// Mitsubishi GX Works2 project: FX3U 485   PLC: FX3U/FX3UC
// FX3U 485

PROGRAM MAIN
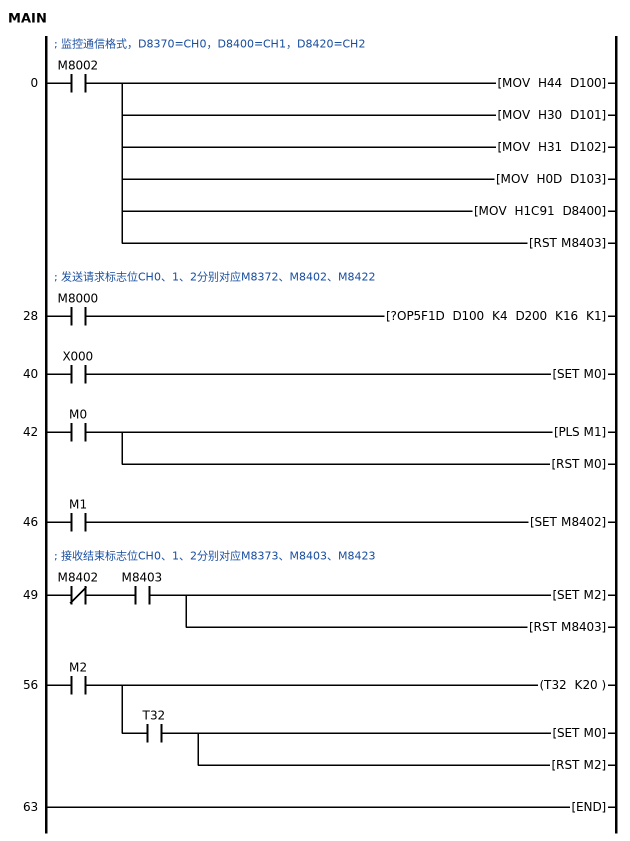
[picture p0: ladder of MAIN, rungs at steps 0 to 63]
; 监控通信格式，D8370=CH0，D8400=CH1，D8420=CH2
0     LD      M8002
      MOV     H44 D100
      MOV     H30 D101
      MOV     H31 D102
      MOV     H0D D103
      MOV     H1C91 D8400
      RST     M8403
; 发送请求标志位CH0、1、2分别对应M8372、M8402、M8422
28    LD      M8000
      ?OP5F1D D100 K4 D200 K16 K1
40    LD      X000
      SET     M0
42    LD      M0
      PLS     M1
      RST     M0
46    LD      M1
      SET     M8402
; 接收结束标志位CH0、1、2分别对应M8373、M8403、M8423
49    LDI     M8402
      AND     M8403
      SET     M2
      RST     M8403
56    LD      M2
      OUT     T32 K20
      AND     T32
      SET     M0
      RST     M2
63    END
END_PROGRAM
